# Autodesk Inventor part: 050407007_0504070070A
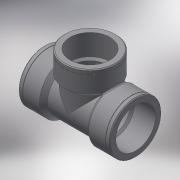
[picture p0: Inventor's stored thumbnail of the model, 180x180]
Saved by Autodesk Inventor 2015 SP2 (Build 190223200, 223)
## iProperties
Created: 2017-05
Part Number: 050407007_0504070070A
Material: Generic
Description: PLASSON THREADED TEE 3/4"
Document SubType Name: Modeling
Designer: KIM
Density: 1 g/cm^3
Appearance: Default
Author: KIM
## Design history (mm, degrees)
derived "050407.ipt"
feature "Solid1::050407.ipt"
tag "TaggingFeature1"
body "Solid1"
other parameters: "d0" = 34, "d2" = 0.5, "d3" = 0.5, "d4" = 31.3521, "d5" = 24.117, "d6" = 19, "d7" = 135 deg, "d8" = 21.85, "d9" = 3.64167, "d19" = 0.48234, "d27" = 19, "d30" = 21.7053, "d31" = 26.5287, "d33" = 180 deg, "d39" = 0, "d45" = 0, "d46" = 26.5287, "d48" = 0, "d50" = 0, "d51" = 0.72351, "Rp_" = 24.117, "H_" = 68, "l_2" = 19
